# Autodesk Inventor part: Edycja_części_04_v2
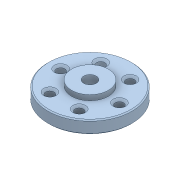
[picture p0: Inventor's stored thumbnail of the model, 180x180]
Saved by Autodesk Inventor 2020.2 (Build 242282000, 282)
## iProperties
Created: 2016-07
Part Number: Edycja_części_04_v2
Material: Stal
Document SubType Name: Modeling
Designer: F.Stasiak
Density: 7.85 g/cm^3
Appearance: Stalowoniebieska — jasna
Manager: www.cadconsulting.pl
Company: Fabian Stasiak CAD Consulting
Author: F.Stasiak
Subject: Zbiór ćwiczeń. Autodesk Inventor 2020. Kurs podstawowy
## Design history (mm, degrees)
sketch "Szkic1"
  geometry: C1 r 40 at (0, 0); 1 further point
  constraints: 1 centre point, 1 coincident
  dimensions: "d0" = 80 diameter of C1
extrude "Wyciągnięcie proste1" new body sketch "Szkic1" distance "d1" = 12; taper "d2" = 0 deg
hole "Otwór1" diameter "d5" = 12; stored, may be unused: countersink angle "d9" = 90 deg, drill point angle "d11" = 118 deg; dims "d3" = 10, "d4" = 10, "d6" = 6, "d7" = 4, "d8" = 2, "d10" = 8
sketch "Szkic2"
  geometry: C1 r 6 at (0, 0) reference; 2 further points
  constraints: 1 horizontal alignment
  dimensions: "d34" = 28 distance of C1.centre point (-28, 0)
hole "Otwór2" sketch "Szkic2" at (-28, 0) diameter "d13" = 8; stored, may be unused: countersink angle "d17" = 90 deg, drill point angle "d19" = 118 deg; dims "d14" = 6, "d15" = 12, "d16" = 2, "d18" = 8
pattern_circular "Szyk kołowy1" dims angle "d21" = 360 deg
chamfer "Faza1" distance "d23" = 1; stored, may be unused: second distance "d24" = 2, angle "d25" = 45 deg
sketch "Szkic4"
  geometry: C1 r 6 at (0, 0) reference; C2 r 39 at (0, 0) reference; C3 r 17.5 at (0, 0)
  constraints: 1 centre point, 1 coincident
  dimensions: "d31" = 35 diameter of C3
extrude "Wyciągnięcie proste3" join sketch "Szkic4" distance "d32" = 5; taper "d33" = 0 deg
node "Bryła1"
